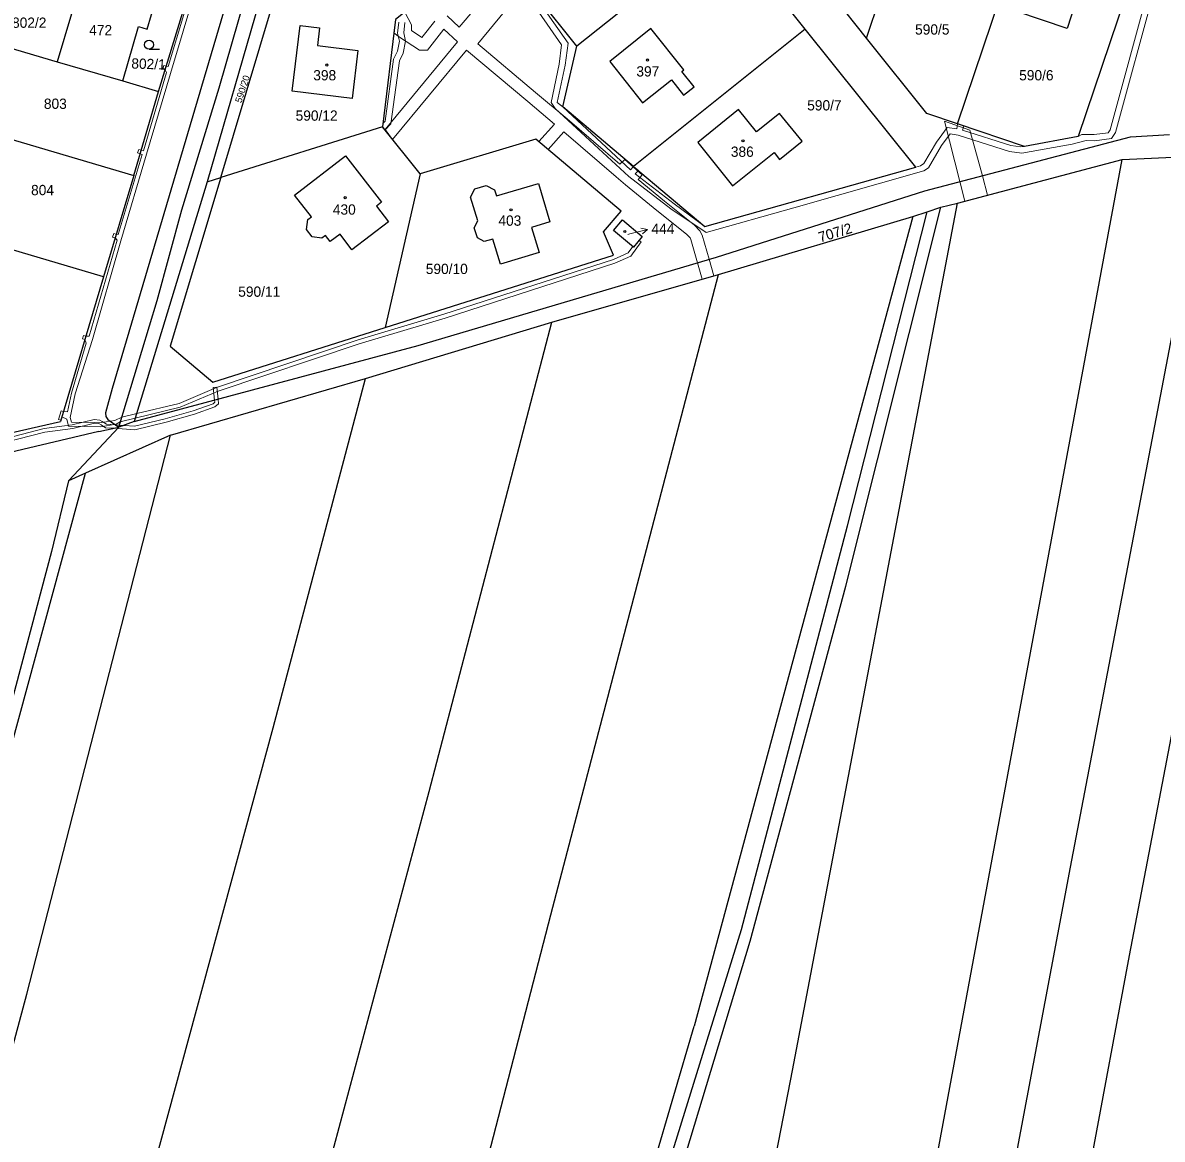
# Model space of a CAD drawing. Extents: x -701211 to -698780, y -1014269 to -1012378.
# Drawn here: x -700673.2 to -700484.6, y -1013587.7 to -1013402.8 of the extents above; entities that cross this region are included whole.
import ezdxf
from ezdxf.enums import TextEntityAlignment as Align

# ---------------------------------------------------------------- set-up
doc = ezdxf.new("R2010")
doc.units = 0
doc.header["$LTSCALE"] = 0.68
for name, color, linetype, lineweight in [('1', 7, 'Continuous', 25), ('13', 7, 'Continuous', 13), ('3', 7, 'Continuous', 25), ('5', 7, 'Continuous', 25), ('7', 7, 'Continuous', 13)]:
    doc.layers.add(name, color=color, linetype=linetype, lineweight=lineweight)
doc.layers.add('2', color=7, linetype='Continuous')

msp = doc.modelspace()

# ---------------------------------------------------------------- linework, layer by layer
at = {"layer": '1'}
for p, q in [((-700615.1, -1013317.2), (-700658.4, -1013463.4)), ((-700533.5, -1013405.37), (-700524.66, -1013379.16)), ((-700518.44, -1013419.59), (-700506.69, -1013384.75)), ((-700557.02, -1013387.18), (-700581.46, -1013406.73)), ((-700543.65, -1013403.89), (-700557.02, -1013387.18)), ((-700640.66, -1013413.61), (-700634.46, -1013392.05)), ((-700581.46, -1013406.73), (-700590.9, -1013394.94)), ((-700533.5, -1013405.37), (-700542.41, -1013394.23)), ((-700652.62, -1013403.88), (-700651.18, -1013398.97)), ((-700650.74, -1013414.21), (-700646.46, -1013400.36)), ((-700634.11, -1013399.59), (-700642.67, -1013429.18)), ((-700640.42, -1013428.47), (-700631.83, -1013399.87)), ((-700500.27, -1013403.77), (-700508.65, -1013401)), ((-700498.9, -1013399.53), (-700500.27, -1013403.77)), ((-700665.13, -1013401.38), (-700667.51, -1013409.28)), ((-700656.64, -1013412.47), (-700654.05, -1013403.45)), ((-700654.05, -1013403.45), (-700652.62, -1013403.88)), ((-700628.58, -1013414.19), (-700627.27, -1013403.27)), ((-700627.27, -1013403.27), (-700624.05, -1013403.66)), ((-700624.05, -1013403.66), (-700624.4, -1013406.63)), ((-700569.21, -1013403.81), (-700576.03, -1013409.26)), ((-700543.65, -1013403.89), (-700572.06, -1013426.62)), ((-700563.76, -1013410.64), (-700569.21, -1013403.81)), ((-700525.37, -1013426.72), (-700543.65, -1013403.89)), ((-700680.12, -1013405.57), (-700667.51, -1013409.28)), ((-700624.4, -1013406.63), (-700617.7, -1013407.42)), ((-700583.76, -1013416.75), (-700581.46, -1013406.73)), ((-700523.5, -1013417.88), (-700533.5, -1013405.37)), ((-700617.7, -1013407.42), (-700618.65, -1013415.36)), ((-700667.51, -1013409.28), (-700656.64, -1013412.47)), ((-700576.03, -1013409.26), (-700570.58, -1013416.09)), ((-700564.06, -1013410.88), (-700563.76, -1013410.64)), ((-700656.64, -1013412.47), (-700650.74, -1013414.21)), ((-700570.58, -1013416.09), (-700565.81, -1013412.28)), ((-700565.81, -1013412.28), (-700563.79, -1013414.82)), ((-700562.03, -1013413.42), (-700564.06, -1013410.88)), ((-700654.83, -1013428.11), (-700650.74, -1013414.21)), ((-700618.65, -1013415.36), (-700628.58, -1013414.19)), ((-700563.79, -1013414.82), (-700562.03, -1013413.42)), ((-700572.06, -1013426.62), (-700583.76, -1013416.75)), ((-700554.69, -1013417.22), (-700561.46, -1013422.65)), ((-700551.72, -1013420.89), (-700554.69, -1013417.22)), ((-700547.89, -1013417.84), (-700551.72, -1013420.89)), ((-700544.16, -1013422.45), (-700547.89, -1013417.84)), ((-700518.44, -1013419.59), (-700523.5, -1013417.88)), ((-700684.28, -1013419.45), (-700654.83, -1013428.11)), ((-700613.64, -1013420.05), (-700640.42, -1013428.47)), ((-700607.4, -1013427.85), (-700613.64, -1013420.05)), ((-700507.35, -1013423.32), (-700518.44, -1013419.59)), ((-700523.87, -1013430.67), (-700489.8, -1013421.72)), ((-700489.8, -1013421.72), (-700483.38, -1013421.33)), ((-700588.27, -1013422.09), (-700607.4, -1013427.85)), ((-700574.14, -1013434.02), (-700588.27, -1013422.09)), ((-700561.46, -1013422.65), (-700555.71, -1013429.86)), ((-700547.9, -1013425.47), (-700544.16, -1013422.45)), ((-700628.19, -1013431.37), (-700619.74, -1013424.88)), ((-700619.74, -1013424.88), (-700613.83, -1013432.56)), ((-700555.71, -1013429.86), (-700548.8, -1013424.33)), ((-700548.8, -1013424.33), (-700547.9, -1013425.47)), ((-700518.45, -1013432.68), (-700491.2, -1013425.47)), ((-700512.7, -1013541.3), (-700491.2, -1013425.47)), ((-700499.72, -1013542.66), (-700477.27, -1013424.86)), ((-700491.2, -1013425.47), (-700477.27, -1013424.86)), ((-700572.06, -1013426.62), (-700560.26, -1013436.59)), ((-700560.26, -1013436.59), (-700525.37, -1013426.72)), ((-700642.67, -1013429.18), (-700654.73, -1013468.88)), ((-700640.42, -1013428.47), (-700648.78, -1013456.36)), ((-700642.67, -1013429.18), (-700640.42, -1013428.47)), ((-700607.4, -1013427.85), (-700613.2, -1013453.3)), ((-700594.78, -1013431.51), (-700587.82, -1013429.43)), ((-700587.82, -1013429.43), (-700585.92, -1013435.8)), ((-700625.41, -1013434.97), (-700628.19, -1013431.37)), ((-700599.08, -1013431.7), (-700598.34, -1013430.33)), ((-700598.34, -1013430.33), (-700596.48, -1013429.77)), ((-700596.48, -1013429.77), (-700595.09, -1013430.48)), ((-700595.09, -1013430.48), (-700594.78, -1013431.51)), ((-700558.32, -1013441.62), (-700523.87, -1013430.67)), ((-700613.83, -1013432.56), (-700614.64, -1013433.19)), ((-700614.64, -1013433.19), (-700612.67, -1013435.78)), ((-700597.86, -1013435.63), (-700599.08, -1013431.7)), ((-700545.79, -1013576.33), (-700518.45, -1013432.68)), ((-700521.2, -1013433.39), (-700518.45, -1013432.68)), ((-700626.01, -1013435.43), (-700625.41, -1013434.97)), ((-700577.04, -1013437.46), (-700574.14, -1013434.02)), ((-700525.83, -1013434.91), (-700562.07, -1013568.98)), ((-700558.02, -1013444.53), (-700525.83, -1013434.91)), ((-700536.94, -1013496.13), (-700521.2, -1013433.39)), ((-700536.64, -1013486.14), (-700523.49, -1013434.15)), ((-700525.83, -1013434.91), (-700523.49, -1013434.15)), ((-700523.49, -1013434.15), (-700521.2, -1013433.39)), ((-700626.22, -1013437.04), (-700626.01, -1013435.43)), ((-700625.26, -1013438.28), (-700626.22, -1013437.04)), ((-700612.67, -1013435.78), (-700618.69, -1013440.41)), ((-700598.48, -1013436.78), (-700597.86, -1013435.63)), ((-700597.93, -1013438.47), (-700598.48, -1013436.78)), ((-700585.92, -1013435.8), (-700588.99, -1013436.74)), ((-700588.99, -1013436.74), (-700587.72, -1013440.9)), ((-700623.66, -1013438.5), (-700625.26, -1013438.28)), ((-700623.07, -1013438.05), (-700623.66, -1013438.5)), ((-700622.28, -1013439.07), (-700623.07, -1013438.05)), ((-700620.67, -1013437.84), (-700622.28, -1013439.07)), ((-700618.69, -1013440.41), (-700620.67, -1013437.84)), ((-700596.8, -1013439.08), (-700597.93, -1013438.47)), ((-700595.36, -1013438.66), (-700596.8, -1013439.08)), ((-700594.13, -1013442.82), (-700595.36, -1013438.66)), ((-700575.42, -1013441.33), (-700577.04, -1013437.46)), ((-700613.2, -1013453.3), (-700575.42, -1013441.33)), ((-700607.76, -1013456.25), (-700558.32, -1013441.62)), ((-700587.72, -1013440.9), (-700594.13, -1013442.82)), ((-700585.77, -1013550.51), (-700558.02, -1013444.53)), ((-700585.62, -1013452.39), (-700558.02, -1013444.53)), ((-700659.83, -1013444.91), (-700666.96, -1013468.87)), ((-700657.31, -1013469.81), (-700650.94, -1013448.84)), ((-700641.7, -1013462.34), (-700613.2, -1013453.3)), ((-700616.46, -1013461.76), (-700585.62, -1013452.39)), ((-700605.91, -1013530.11), (-700585.62, -1013452.39)), ((-700654.73, -1013468.88), (-700607.76, -1013456.25)), ((-700648.78, -1013456.36), (-700641.7, -1013462.34)), ((-700489.96, -1013557.24), (-700470.95, -1013457.54)), ((-700658.4, -1013463.4), (-700659.49, -1013467.43)), ((-700648.76, -1013471.09), (-700616.46, -1013461.76)), ((-700631.73, -1013519.55), (-700616.46, -1013461.76)), ((-700701.43, -1013476.61), (-700666.96, -1013468.87)), ((-700659.49, -1013467.43), (-700659.46, -1013468.05)), ((-700659.46, -1013468.05), (-700659.11, -1013468.52)), ((-700659.11, -1013468.52), (-700657.31, -1013469.81)), ((-700654.73, -1013468.88), (-700657.31, -1013469.81)), ((-700660.57, -1013470.5), (-700699.48, -1013479.65)), ((-700665.63, -1013478.67), (-700657.31, -1013469.81)), ((-700660.57, -1013470.5), (-700657.31, -1013469.81)), ((-700672.52, -1013563.65), (-700648.76, -1013471.09)), ((-700648.76, -1013471.09), (-700662.8, -1013477.4)), ((-700676.43, -1013527.57), (-700662.8, -1013477.4)), ((-700662.8, -1013477.4), (-700665.63, -1013478.67)), ((-700665.63, -1013478.67), (-700668.45, -1013490.39)), ((-700554.23, -1013552.98), (-700536.64, -1013486.14)), ((-700668.45, -1013490.39), (-700676.98, -1013522.39)), ((-700552.76, -1013554.87), (-700536.94, -1013496.13)), ((-700665.02, -1013641.98), (-700631.73, -1013519.55)), ((-700656.69, -1013719.85), (-700605.91, -1013530.11)), ((-700535.23, -1013662.99), (-700512.7, -1013541.3)), ((-700522.57, -1013663.69), (-700499.72, -1013542.66)), ((-700619.53, -1013680.92), (-700585.77, -1013550.51)), ((-700580.5, -1013637.65), (-700554.23, -1013552.98)), ((-700583.8, -1013657.31), (-700552.76, -1013554.87)), ((-700509.91, -1013664.16), (-700489.96, -1013557.24)), ((-700700.39, -1013667.01), (-700672.52, -1013563.65)), ((-700576.27, -1013617.48), (-700562.07, -1013568.98)), ((-700575.8, -1013732.18), (-700545.79, -1013576.33))]:
    msp.add_line(p, q, dxfattribs=at)
for points in [[(-700487.99, -1013390.58), (-700498.46, -1013421.65), (-700507.35, -1013423.32)], [(-700599.37, -1013392.61), (-700611.51, -1013402.32), (-700613.64, -1013420.05)], [(-700650.94, -1013448.84), (-700646.84, -1013433.81), (-700640.66, -1013413.61)], [(-700654.83, -1013428.11), (-700659.83, -1013444.91), (-700689.3, -1013436.16)]]:
    msp.add_lwpolyline(points, dxfattribs=at)
msp.add_lwpolyline([(-700572.09, -1013439.97), (-700575.38, -1013437.24), (-700573.93, -1013435.45), (-700570.63, -1013438.22)], close=True, dxfattribs=at)
at = {"layer": '13'}
for points in [[(-700593.14, -1013394.39), (-700600.92, -1013403.58), (-700602.94, -1013401.7)], [(-700645.13, -1013396.83), (-700649.13, -1013410.08), (-700649.45, -1013410.04), (-700649.64, -1013410.64), (-700649.4, -1013411.07), (-700653.23, -1013424.06), (-700653.6, -1013423.94), (-700653.78, -1013424.53), (-700653.41, -1013424.66), (-700657.41, -1013437.87), (-700657.73, -1013437.84), (-700657.9, -1013438.43), (-700657.59, -1013438.81), (-700662.2, -1013454.74), (-700662.75, -1013454.73), (-700663.12, -1013454.62), (-700663.29, -1013455.19), (-700662.92, -1013455.3), (-700662.67, -1013455.89), (-700665.13, -1013464.14), (-700665.8, -1013467.26), (-700666.47, -1013467.21), (-700666.83, -1013467.08), (-700667.28, -1013468.55), (-700666.9, -1013468.66), (-700666.72, -1013468.06), (-700665.92, -1013468.47), (-700665.6, -1013469.64), (-700660.32, -1013469.71), (-700657.73, -1013469.32), (-700657.04, -1013468.92), (-700654.56, -1013468.32), (-700654.32, -1013467.54), (-700656.8, -1013468.13), (-700657.93, -1013468.68), (-700660.1, -1013469), (-700665.1, -1013468.98), (-700665.32, -1013468.17), (-700664.49, -1013464.3), (-700661.66, -1013455.27), (-700656.95, -1013438.95), (-700652.7, -1013424.6), (-700648.76, -1013411.25), (-700644.54, -1013397.15)], [(-700611.51, -1013402.32), (-700611.77, -1013404.49), (-700610.82, -1013405.21), (-700607.51, -1013407.39), (-700606.21, -1013407.36), (-700603.49, -1013403.92), (-700601.23, -1013406.02), (-700613.21, -1013420.52), (-700611.96, -1013422.15), (-700599.73, -1013407.35), (-700589.57, -1013415.9), (-700585.15, -1013419.62), (-700587.76, -1013422.52), (-700586.23, -1013423.81), (-700583.62, -1013420.92), (-700574.94, -1013428.37), (-700573.43, -1013429.67), (-700568.23, -1013433.91), (-700563.32, -1013437.82), (-700562.73, -1013438.44), (-700562.57, -1013438.73), (-700561.5, -1013442.56), (-700560.73, -1013445.3), (-700558.8, -1013444.75), (-700559.58, -1013441.99), (-700560.71, -1013437.99), (-700561.09, -1013437.26), (-700561.96, -1013436.34), (-700566.97, -1013432.35), (-700571.34, -1013428.79), (-700570.63, -1013427.99), (-700573.54, -1013425.49), (-700574.33, -1013426.26), (-700583.06, -1013418.76), (-700588.29, -1013414.37), (-700597.84, -1013406.33), (-700589.81, -1013396.52)], [(-700587.76, -1013401.06), (-700583.99, -1013406.51), (-700584.38, -1013409.69), (-700585.74, -1013416.06), (-700585.08, -1013417.05), (-700572.88, -1013428.28), (-700565.93, -1013433.66), (-700560.07, -1013437.57), (-700545.54, -1013433.46), (-700524, -1013427.38), (-700523.27, -1013426.83), (-700521.11, -1013423.14), (-700519.69, -1013421.24), (-700518.33, -1013421.43), (-700509.84, -1013424.15), (-700507.82, -1013424.44), (-700499.44, -1013422.95), (-700497.16, -1013422.34), (-700495.76, -1013422.36), (-700492.94, -1013421.98), (-700492.28, -1013420.99), (-700485.7, -1013396.89)], [(-700486.66, -1013396.61), (-700493.2, -1013420.57), (-700493.52, -1013421.04), (-700495.82, -1013421.36), (-700497.84, -1013421.33), (-700498.46, -1013421.65), (-700507.35, -1013423.32), (-700507.99, -1013423.4), (-700509.6, -1013423.17), (-700517.6, -1013420.61), (-700517.4, -1013419.94), (-700518.44, -1013419.59), (-700518.58, -1013420.39), (-700520.15, -1013420.18), (-700521.93, -1013422.58), (-700524.04, -1013426.15), (-700524.57, -1013426.55), (-700525.37, -1013426.72), (-700560.26, -1013436.59), (-700565.35, -1013432.84), (-700571.8, -1013427.85), (-700571.25, -1013427.3), (-700572.06, -1013426.62), (-700572.59, -1013427.2), (-700583.76, -1013416.75), (-700584.7, -1013416.04), (-700583.4, -1013409.87), (-700582.92, -1013406.24), (-700586.98, -1013400.44)], [(-700605, -1013402.6), (-700607.1, -1013405.26), (-700608.84, -1013404.12), (-700608.84, -1013403.19), (-700609.95, -1013401.07)], [(-700610.91, -1013402.73), (-700611.13, -1013404.55), (-700610.83, -1013405.9), (-700611.18, -1013407.55), (-700611.79, -1013408.88), (-700613.18, -1013419.12), (-700613.58, -1013419.54), (-700613.64, -1013420.05), (-700613.21, -1013420.58), (-700612.24, -1013419.59), (-700610.81, -1013409.16), (-700610.22, -1013407.87), (-700609.81, -1013405.9), (-700610.11, -1013404.49), (-700609.92, -1013402.81)], [(-700680.56, -1013473.45), (-700669.54, -1013470.62), (-700664.89, -1013470), (-700661.34, -1013469.14), (-700660.62, -1013469.19), (-700660.23, -1013469.43), (-700659.5, -1013469.88), (-700658.11, -1013469.98), (-700657.31, -1013469.81), (-700656.43, -1013469.49), (-700657.2, -1013469.44), (-700659.32, -1013469.3), (-700660.05, -1013468.84), (-700660.44, -1013468.61), (-700661.38, -1013468.54), (-700665.01, -1013469.4), (-700669.66, -1013470.04), (-700680.7, -1013472.87)]]:
    msp.add_lwpolyline(points, dxfattribs=at)
for points in [[(-700649.45, -1013410.04), (-700649.82, -1013409.93), (-700650.01, -1013410.53), (-700649.64, -1013410.64)], [(-700518.04, -1013429.14), (-700517.22, -1013432.35), (-700513.47, -1013431.36), (-700514.33, -1013428.17), (-700516.38, -1013420.62), (-700520.58, -1013419.13)], [(-700653.99, -1013423.82), (-700654.17, -1013424.4), (-700653.78, -1013424.53), (-700653.6, -1013423.94)], [(-700658.32, -1013438.31), (-700657.9, -1013438.43), (-700657.73, -1013437.84), (-700658.13, -1013437.71)], [(-700575.16, -1013442.66), (-700572.55, -1013441.47), (-700570.82, -1013439.12), (-700571.17, -1013438.87), (-700572.09, -1013439.97), (-700572.19, -1013439.88), (-700572.97, -1013440.95), (-700575.4, -1013442.04), (-700603.48, -1013451.11), (-700617.69, -1013455.36), (-700641.11, -1013463.21), (-700647.31, -1013465.86), (-700654.32, -1013467.54), (-700654.56, -1013468.32), (-700647.11, -1013466.5), (-700640.85, -1013463.81), (-700617.49, -1013455.98), (-700603.28, -1013451.75)], [(-700656.43, -1013469.49), (-700657.31, -1013469.81), (-700657.51, -1013470.02), (-700656.75, -1013470.07), (-700654.63, -1013470.25), (-700649.47, -1013468.97), (-700644.78, -1013467.63), (-700641.38, -1013466.43), (-700640.78, -1013465.94), (-700640.87, -1013465.15), (-700641.09, -1013463.17), (-700641.69, -1013463.23), (-700641.46, -1013465.31), (-700641.42, -1013465.68), (-700641.68, -1013465.91), (-700644.98, -1013467.07), (-700649.63, -1013468.39), (-700654.67, -1013469.65)]]:
    msp.add_lwpolyline(points, close=True, dxfattribs=at)
at = {"layer": '3'}
msp.add_line((-700652.283, -1013407.23), (-700650.533, -1013407.23), dxfattribs=at)
msp.add_circle((-700652.2829, -1013406.4798), 0.75, dxfattribs=at)
at = {"layer": '5'}
for centre in [(-700622.8568, -1013409.8392), (-700569.7568, -1013409.0092), (-700553.9668, -1013422.3992), (-700619.8168, -1013431.7892), (-700592.3568, -1013433.7992), (-700573.5168, -1013437.4092)]:
    msp.add_circle(centre, 0.175, dxfattribs=at)
at = {"layer": '7'}
msp.add_line((-700569.768, -1013437.064), (-700570.861, -1013436.82), dxfattribs=at)
msp.add_lwpolyline([(-700573.04, -1013437.88), (-700572.68, -1013437.79), (-700569.768, -1013437.064), (-700570.619, -1013437.792)], dxfattribs=at)

# ---------------------------------------------------------------- texts
at = {"layer": '2'}
for s, p in [('802/2', (-700672.12, -1013403.675)), ('803', (-700667.799, -1013417.095)), ('804', (-700669.919, -1013431.385)), ('444', (-700567.209, -1013437.785))]:
    msp.add_text(s, height=1.7, dxfattribs=at).set_placement(p, align=Align.CENTER)
for s, p in [('590/5', (-700525.47, -1013404.795)), ('472', (-700662.19, -1013404.915)), ('398', (-700625.1, -1013412.375)), ('397', (-700571.61, -1013411.735)), ('590/6', (-700508.24, -1013412.375)), ('590/7', (-700543.33, -1013417.355)), ('590/12', (-700628.02, -1013419.055)), ('386', (-700555.97, -1013425.035)), ('430', (-700621.86, -1013434.605)), ('403', (-700594.45, -1013436.445)), ('590/10', (-700606.47, -1013444.435)), ('590/11', (-700637.52, -1013448.205))]:
    msp.add_text(s, height=1.7, dxfattribs=at).set_placement(p)
for s, rotation, p in [('802/1', 358, (-700655.244, -1013410.404)), ('707/2', 17, (-700541.175, -1013439.226))]:
    msp.add_text(s, height=1.7, rotation=rotation, dxfattribs=at).set_placement(p)
msp.add_text('590/20', height=1.14, rotation=72, dxfattribs=at).set_placement((-700636.2796, -1013413.9776), align=Align.CENTER)

doc.saveas('drawing.dxf')
